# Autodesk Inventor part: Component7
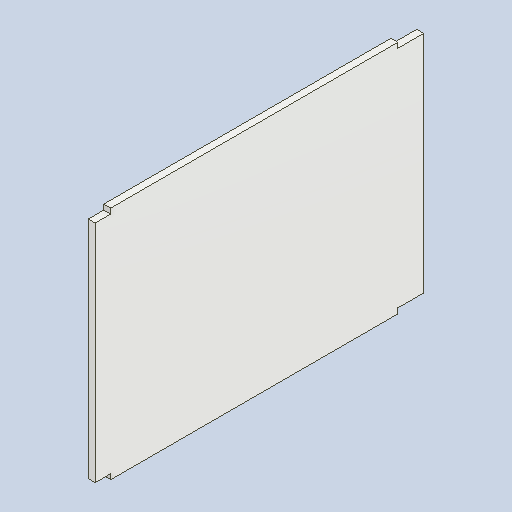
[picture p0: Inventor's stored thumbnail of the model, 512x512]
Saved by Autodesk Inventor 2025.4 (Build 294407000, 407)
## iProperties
Created: 2026-06
Part Number: Component7
Material: Generic
Document SubType Name: Modeling
Designer: AdminForWorker
Density: 1 g/cm^3
Appearance: Default
Title: Component7
Author: AdminForWorker
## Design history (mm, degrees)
feature "Body1"
body "Solid1"
